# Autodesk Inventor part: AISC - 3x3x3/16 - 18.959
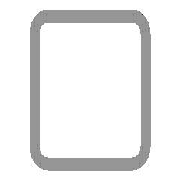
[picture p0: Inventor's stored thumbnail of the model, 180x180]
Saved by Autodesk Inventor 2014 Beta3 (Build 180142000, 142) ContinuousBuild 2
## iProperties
IsCustomPart: 1
Created: 2011-11
Part Number: AISC - 3x3x3/16 - 18.959
Material: Steel, Mild
Description: Tube
Document SubType Name: Modeling
Standard: ANSI
Designer: Thom Tremblay
Standards Organization: ANSI
Language: en-US
Size Designation: 3x3x3/16
Categories: <MemberInstance><Categories><Category DisplayName="Structural Shapes" InternalName="089c4875-fa83-4c05-b084-43b9cc11f5ed" Mnemonic="GRDR"><CategoryParameter Dis
Stock Number: 3x3x3/16
Density: 7.86 g/cm^3
Appearance: Steel
_CCFamilyMember: 9
_CCFamilyDisplayName: ANSI AISC (Square) - Tube
_FrameMemberDoc: Frame Member File
_Version: 15.0.0
_GetPNFromCC: 1
G_L: 18.959 in
G_W: 3.000 in
G_H: 3.000 in
Author: Thom Tremblay
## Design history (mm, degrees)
node "Start plane"
node "End plane"
node "Driven Length"
  sketch "Sketch3"
    geometry: L1 (0, 0)-(10, 0) reference
    constraints: 2 end point, 1 horizontal
  workplane "Work Plane3"
  sketch "Sketch4"
    geometry: L1 (-2, 0)-(12, 0) reference; L2 (-53.34, 481.559)-(53.34, 481.559) reference
    dimensions: "d19" = 481.55872 distance between parallel lines of L1 L2 (derived)
sketch "Sweep Path"
  geometry: L1 through (609.6, 0) direction (1, 0); 1 other entity
  constraints: 5 horizontal
node "Orientation Work Plane"
feature "Body" dims "d20" = 0
body "Solid1"
sketch "Sketch"
  geometry: L1 (-38.1, -28.575)-(-38.1, 28.575); L2 (-28.575, 38.1)-(28.575, 38.1); L3 (38.1, 28.575)-(38.1, -28.575); L4 (28.575, -38.1)-(-28.575, -38.1); L5 (-28.575, 33.337)-(28.575, 33.338); L6 (33.338, 28.575)-(33.338, -28.575); L7 (28.575, -33.337)-(-28.575, -33.338); L8 (-33.338, -28.575)-(-33.338, 28.575); L9 (0, 36.948)-(0, -36.948); L10 (-23.079, 0)-(23.079, 0); A1 r 9.525 centre (-28.575, -28.575) between (-38.1, -28.575) and (-28.575, -38.1); A2 r 9.525 centre (-28.575, 28.575) between (-28.575, 38.1) and (-38.1, 28.575); A3 r 9.525 centre (28.575, 28.575) between (38.1, 28.575) and (28.575, 38.1); A4 r 9.525 centre (28.575, -28.575) between (28.575, -38.1) and (38.1, -28.575); A5 r 4.763 centre (-28.575, 28.575) between (-28.575, 33.337) and (-33.338, 28.575); A6 r 4.763 centre (28.575, 28.575) between (33.338, 28.575) and (28.575, 33.338); A7 r 4.763 centre (28.575, -28.575) between (28.575, -33.337) and (33.338, -28.575); A8 r 4.763 centre (-28.575, -28.575) between (-33.338, -28.575) and (-28.575, -33.338)
  constraints: 20 end point, 16 point on circle, 8 centre point, 8 tangent, 4 parallel, 3 equal radius, 2 perpendicular, 7 other
  dimensions: "d10" = 76.2 distance between parallel lines of L2 L4 (= G_H); "d11" = 76.2 distance between parallel lines of L1 L3 (= G_W); "d12" = 4.7625 distance between parallel lines of L3 L6 (= G_T); "d15" = 38.1 distance between parallel lines of L2 L10 (= 0.5 x d10); "d16" = 38.1 distance between parallel lines of L9 L3 (= 0.5 x d11); "d17" = 9.525 radius of A1 (= G_IR)
other parameters: "G_W" = 76.2 [user parameter; used in 1 equation term], "G_H" = 76.2 [user parameter; used in 1 equation term], "G_T" = 4.7625 [user parameter; used in 1 equation term], "G_IR" = 9.525 [user parameter; used in 1 equation term], "G_L" = 481.55872 (= d19) [user parameter], "G_OFFSET_START" = 0 [user parameter; used in 1 equation term], "G_OFFSET_END" = 0 [user parameter; used in 1 equation term], "d13" = 0 (computed from G_OFFSET_START), "d14" = 481.55872 (= G_OFFSET_END + B_L), "B_L" = 481.55872 [user parameter; used in 1 equation term], "d18" = 90 deg
